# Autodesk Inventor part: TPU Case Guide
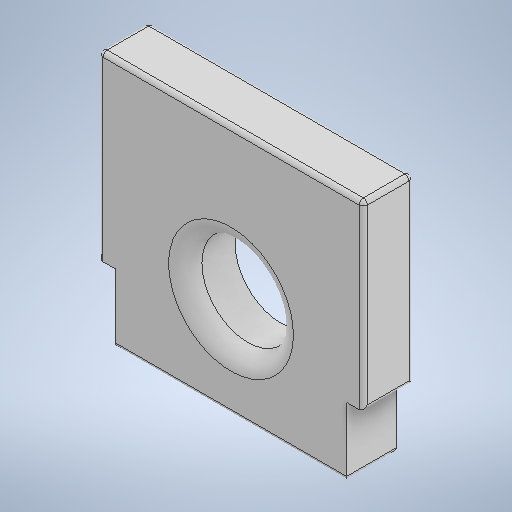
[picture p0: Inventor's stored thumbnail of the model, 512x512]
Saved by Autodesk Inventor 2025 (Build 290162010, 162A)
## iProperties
Created: 2023-12
Part Number: TPU Case Guide
Material: Generic
Document SubType Name: Modeling
Designer: Andrew
Density: 1 g/cm^3
Appearance: Default
Author: Andrew
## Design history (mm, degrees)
sketch "Sketch1"
  geometry: L1 (-17.653, 19.05)-(17.653, 19.05); L2 (17.653, 19.05)-(17.653, -19.05); L3 (17.653, -19.05)-(-17.653, -19.05); L4 (-17.653, -19.05)-(-17.653, 19.05); 1 further point
  constraints: 8 end point, 2 parallel, 1 horizontal, 1 perpendicular
  dimensions: "d0" = 35.306 distance between parallel lines of L2 L4; "d1" = 38.1 distance between parallel lines of L3 L1; "d2" = 17.653 distance from line of point (0, 0) L4 (= 0.5 x d0); "d3" = 19.05 distance from line of point (0, 0) L1 (= 0.5 x d1)
extrude "Extrusion1" new body sketch "Sketch1" distance "d4" = 7.62; taper "d5" = 0 deg
sketch "Sketch3"
  geometry: L1 (35.306, 0)-(35.306, -7.62) reference; L2 (35.306, -7.62)-(37.846, -7.62); L3 (37.846, -7.62)-(37.846, 0); L4 (37.846, 0)-(35.306, 0); L5 (35.306, 0)-(35.306, -7.62); L6 (0, 0)-(0, -7.62) reference; L7 (0, -7.62)-(-2.54, -7.62); L8 (-2.54, -7.62)-(-2.54, 0); L9 (-2.54, 0)-(0, 0); L10 (0, 0)-(0, -7.62); L11 (35.306, 0)-(0, 0) reference; L12 (35.306, -7.62)-(0, -7.62) reference; 4 further points
  constraints: 16 end point, 4 parallel, 4 point on line, 2 horizontal, 2 perpendicular, 1 midpoint
  dimensions: "d7" = 2.54 distance between parallel lines of L1 L3; "d8" = 2.54 distance between parallel lines of L8 L6 (= d7); "d48" = 0 distance between parallel lines of L12 L2; "d49" = 0 distance between parallel lines of L11 L4
extrude "Extrusion2" join sketch "Sketch3" distance "d10" = 27.686; taper "d11" = 0 deg
fillet "Fillet1" dims "d12" = 0.635
sketch "Sketch6" dims "d50" = 40.386 (derived)
  geometry: L1 (-17.018, -19.05)-(17.018, -19.05) reference; C1 r 6.985 at (0, -3.81); 19 further points; 2 other entities
  constraints: 1 centre point, 2 other
  dimensions: "d20" = 13.97 diameter of C1; "d51" = 20.193 dimension on C1.centre (= 0.5 x d50); "d53" = 15.24 distance from line of C1.centre L1
extrude "Extrusion4" cut sketch "Sketch6" extent not by distance; stored distance "d24" = 0; taper "d25" = 0 deg
fillet "Fillet4" dims "d54" = 2.54
body "Solid1"
